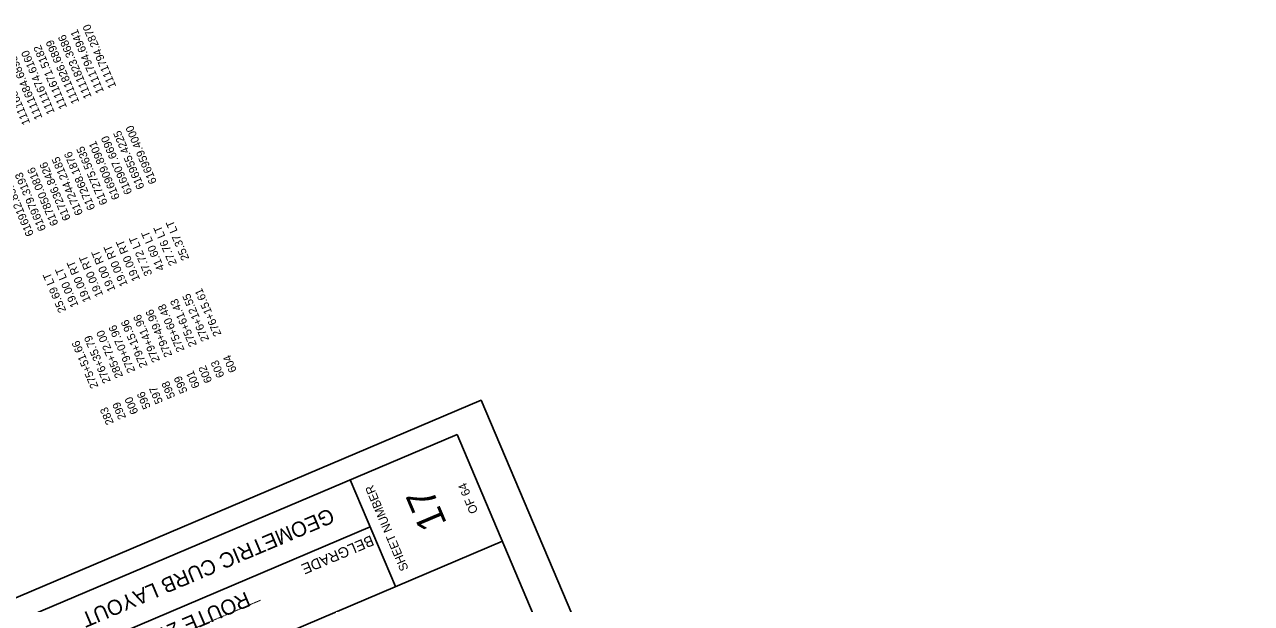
# Model space of a CAD drawing. Extents: x 1111260 to 1112147, y 617053 to 618212.
# Drawn here: x 1111569 to 1112098, y 617963 to 618212 of the extents above; entities that cross this region are included whole.
import ezdxf

# ---------------------------------------------------------------- set-up
doc = ezdxf.new("R2010")
doc.units = 0
for name, color, linetype in [('ANNOTATION', 7, 'Continuous'), ('BORDER', 7, 'Continuous'), ('BRIDGE_TITLE', 7, 'Continuous'), ('HIGHWAY_TITLE', 7, 'Continuous'), ('PLOT BOUNDARY', 7, 'Continuous')]:
    doc.layers.add(name, color=color, linetype=linetype)

msp = doc.modelspace()

# ---------------------------------------------------------------- linework, layer by layer
at = {"layer": 'BORDER'}
for p, q in [((1111755.5, 618035.73), (1111272.23, 617830.6)), ((1112068.1, 617299.33), (1111755.51, 618035.74)), ((1111729.01, 617970.17), (1111709.47, 618016.19)), ((1111718.09, 617995.9), (1111557, 617927.52)), ((1111775.03, 617989.7), (1111291.77, 617784.57))]:
    msp.add_line(p, q, dxfattribs=at)
at = {"layer": 'PLOT BOUNDARY'}
msp.add_lwpolyline([(1112097.99, 617268.06), (1111765.87, 618050.49), (1111259.59, 617835.59), (1111591.71, 617053.16)], close=True, dxfattribs=at)

# ---------------------------------------------------------------- texts
at = {"layer": 'ANNOTATION'}
for s, p in [('1111794.6941', (1111603.33, 618183.49)), ('1111794.2870', (1111608.64, 618185.74)), ('1111826.6899', (1111592.73, 618178.99)), ('1111823.3686', (1111598.03, 618181.24)), ('1111684.6898', (1111576.82, 618172.23)), ('1111674.6160', (1111582.12, 618174.49)), ('1111671.5182', (1111587.42, 618176.74)), ('1111687.7876', (1111571.51, 618169.98)), ('616959.4000', (1111626.15, 618144.49)), ('616909.8901', (1111610.23, 618137.74)), ('616907.6690', (1111615.54, 618139.99)), ('616955.4225', (1111620.84, 618142.24)), ('617268.1876', (1111599.63, 618133.24)), ('617275.5635', (1111604.93, 618135.49)), ('617236.8426', (1111589.02, 618128.73)), ('617244.2185', (1111594.32, 618130.99)), ('616912.8314', (1111573.11, 618121.98)), ('616979.3193', (1111578.41, 618124.23)), ('617850.0816', (1111583.72, 618126.48)), ('27.76 LT', (1111634.81, 618109.32)), ('25.37 LT', (1111640.12, 618111.57)), ('37.72 LT', (1111624.21, 618104.82)), ('41.60 LT', (1111629.51, 618107.07)), ('19.00 RT', (1111608.3, 618098.07)), ('19.00 RT', (1111613.6, 618100.32)), ('19.00 RT', (1111618.9, 618102.57)), ('19.00 RT', (1111597.69, 618093.57)), ('19.00 RT', (1111602.99, 618095.82)), ('25.69 LT', (1111587.08, 618089.06)), ('19.00 LT', (1111592.39, 618091.31)), ('276+15.61', (1111654, 618078.86)), ('275+61.43', (1111643.4, 618074.36)), ('276+12.55', (1111648.7, 618076.61)), ('279+49.96', (1111632.79, 618069.86)), ('275+60.48', (1111638.09, 618072.11)), ('279+07.96', (1111616.88, 618063.1)), ('279+15.96', (1111622.18, 618065.35)), ('279+41.96', (1111627.49, 618067.6)), ('276+35.79', (1111606.27, 618058.6)), ('285+72.00', (1111611.58, 618060.85)), ('275+51.66', (1111600.97, 618056.35)), ('603', (1111655.33, 618061)), ('604', (1111660.63, 618063.25)), ('601', (1111644.72, 618056.49)), ('602', (1111650.03, 618058.74)), ('598', (1111634.11, 618051.99)), ('599', (1111639.42, 618054.24)), ('600', (1111618.2, 618045.24)), ('596', (1111623.51, 618047.49)), ('597', (1111628.81, 618049.74)), ('283', (1111607.6, 618040.74)), ('299', (1111612.9, 618042.99))]:
    msp.add_text(s, height=3.45, rotation=113, dxfattribs=at).set_placement(p)
at = {"layer": 'BORDER'}
for s, height, rotation, p in [('SHEET NUMBER', 3.7264, 113, (1111734.66, 617977.81)), ('OF 64', 3.726, 113, (1111764.66, 618002.5)), ('17', 12.097, 113, (1111751.25, 617997.38)), ('GEOMETRIC CURB LAYOUT', 6.5214, 203, (1111700.8, 618004.17))]:
    msp.add_text(s, height=height, rotation=rotation, dxfattribs=at).set_placement(p)
at = {"layer": 'BRIDGE_TITLE'}
for s, height, p in [('BELGRADE', 4.536, (1111718.38, 617992.38)), ('_____________', 4.5358, (1111671.18, 617963.24))]:
    msp.add_text(s, height=height, rotation=203, dxfattribs=at).set_placement(p)
at = {"layer": 'HIGHWAY_TITLE'}
msp.add_text('ROUTE 27', height=6.521, rotation=203, dxfattribs=at).set_placement((1111664.54, 617968.11))

doc.saveas('drawing.dxf')
